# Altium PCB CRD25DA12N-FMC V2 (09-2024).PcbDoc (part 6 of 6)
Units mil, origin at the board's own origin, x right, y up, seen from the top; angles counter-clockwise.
Board outline 8000 x 8000 mil, 6 copper layers (Top Layer, Layer 2, Layer 3, Layer 4, Layer 5, Bottom Layer), stack 91 mil thick; 602 components, 333 nets, 1670 pads, 639 vias.
Unrouted connection lines stored in the file: 1.
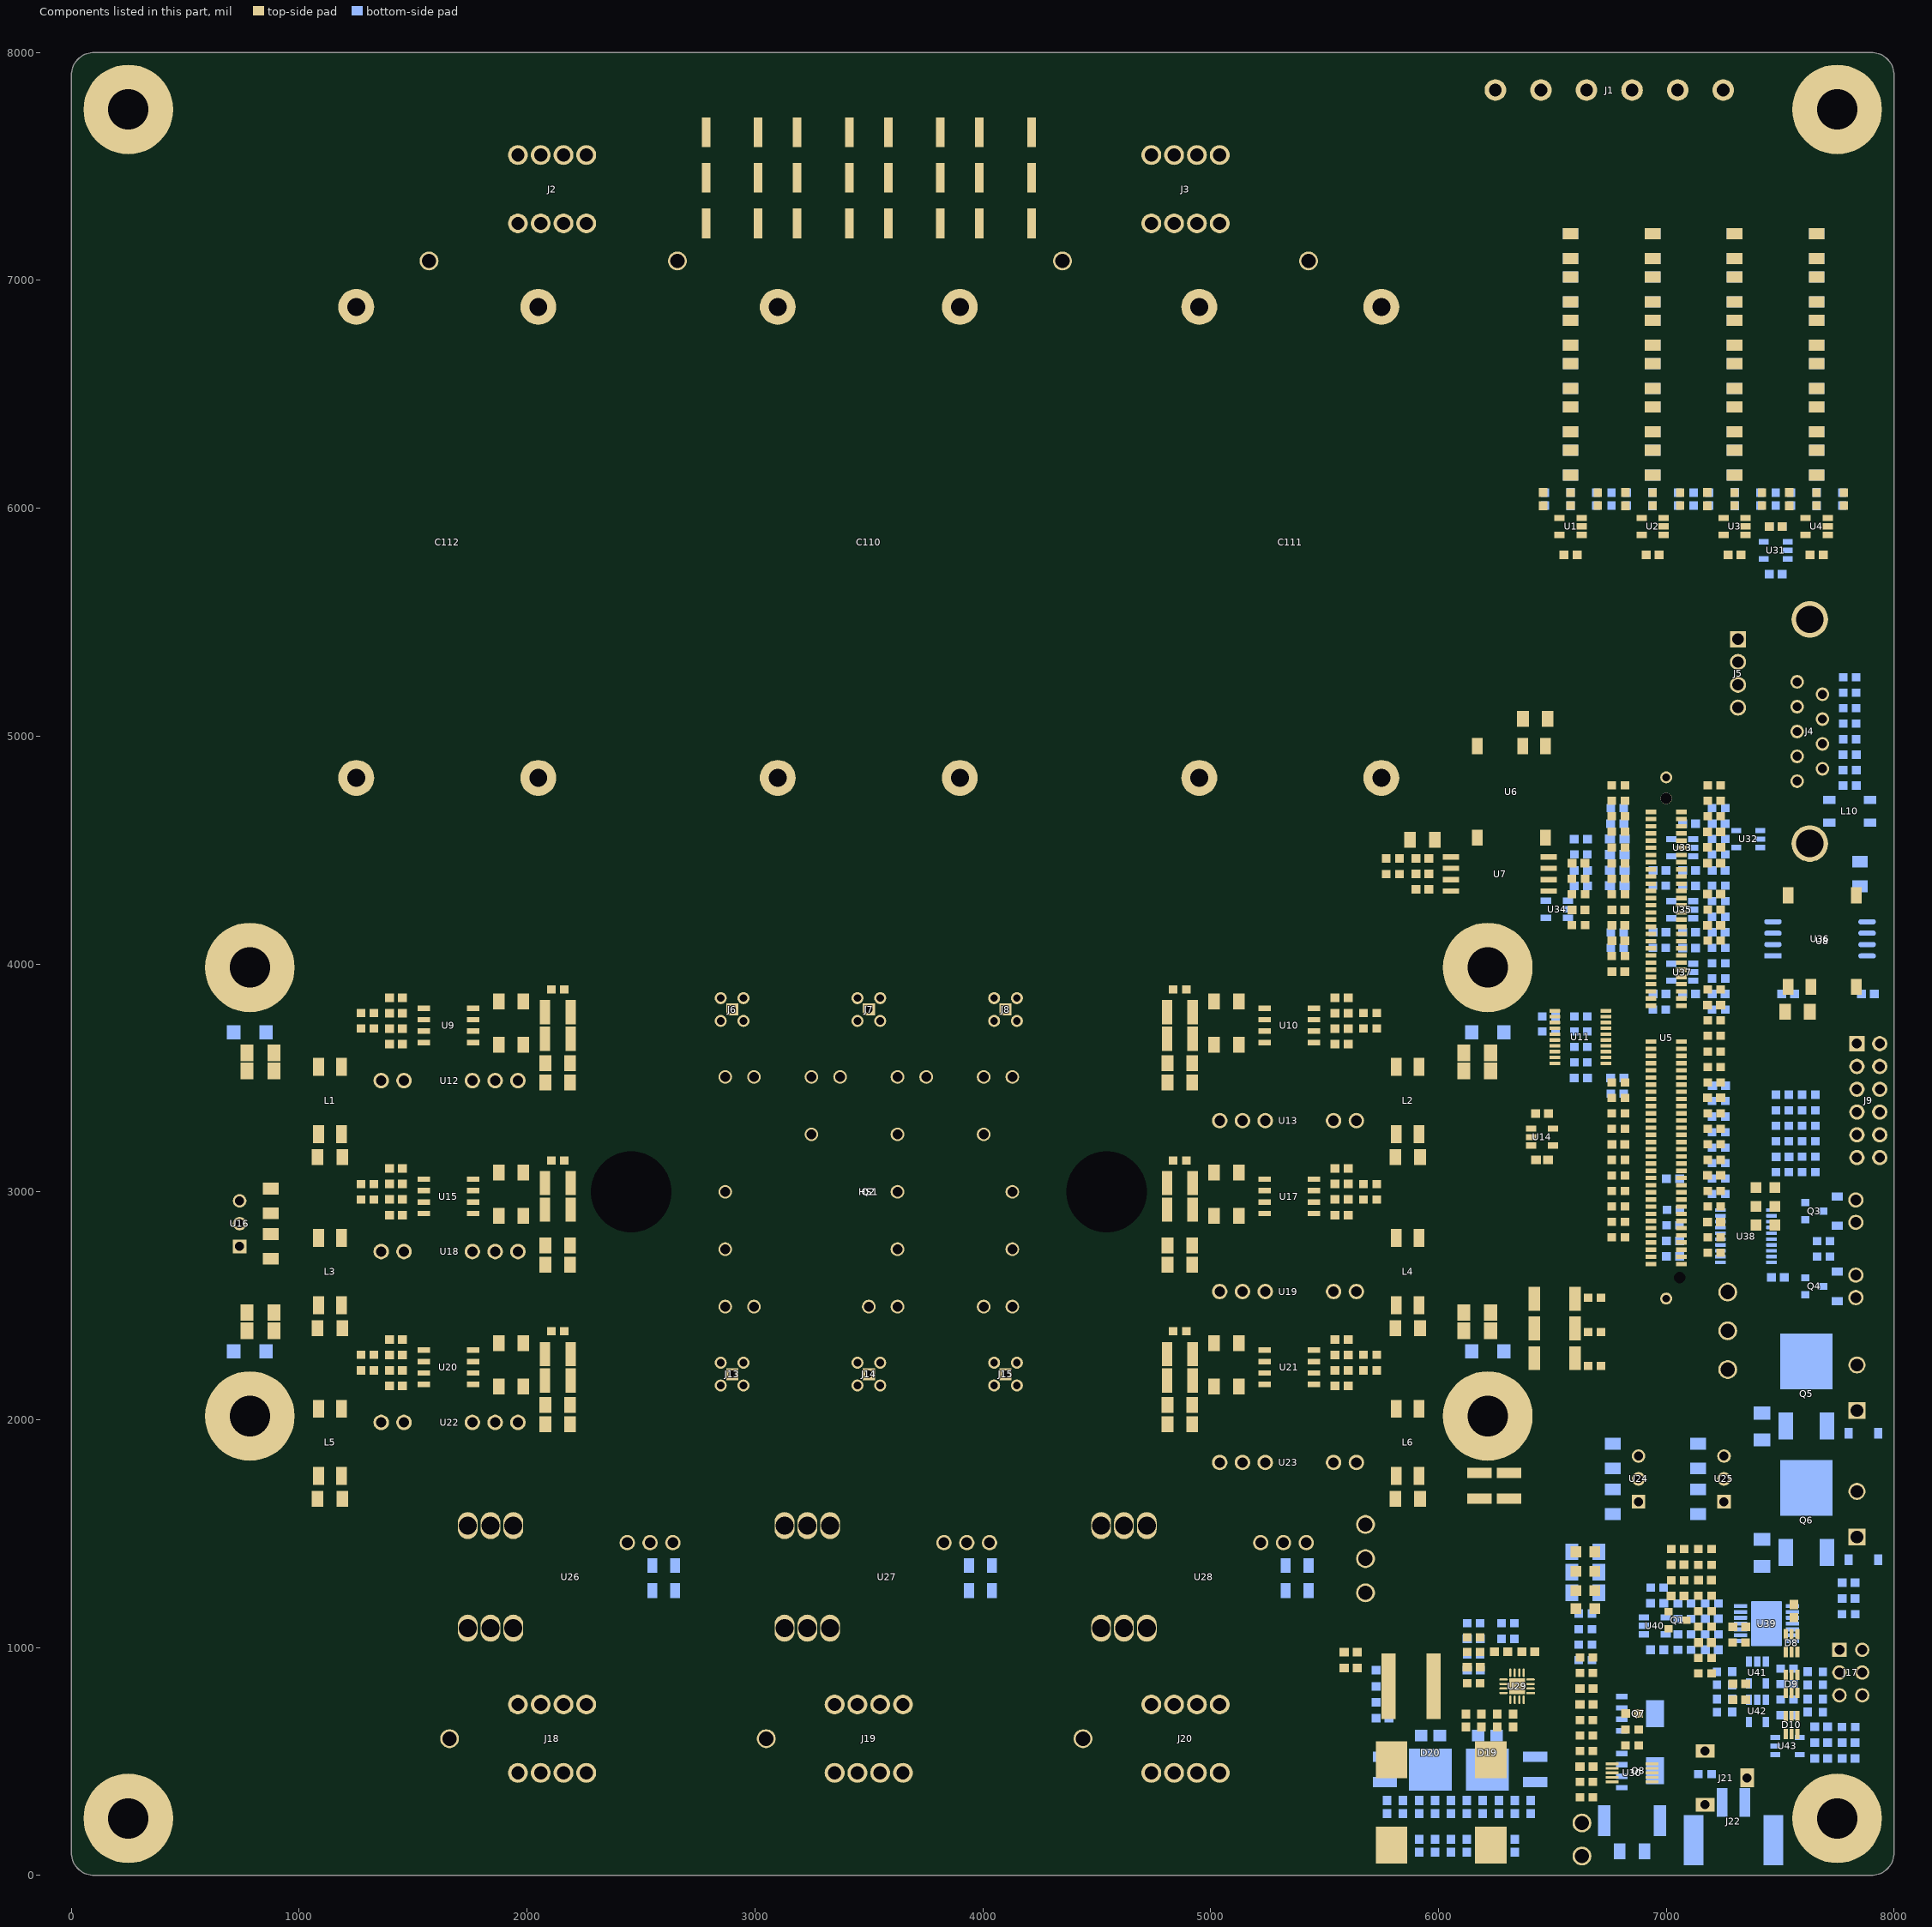
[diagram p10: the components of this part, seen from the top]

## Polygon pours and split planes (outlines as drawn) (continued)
+15V on Bottom Layer "Bottom Layer-+15V 1" (solid, pour order 1128): 3980,1334.96 3980,1489.91 ccw(c3954.91,1489.91) 3954.98,1515 3914.95,1515 ccw(c3915.07,1489.93) 3890,1489.92 3890,1405 3890,1391.3 3890,1334.98 ccw(c3915.03,1335.03) 3914.94,1310 3954.97,1310 ccw(c3954.97,1335.03)
GND on Bottom Layer "Bottom Layer-GND 2" (solid, pour order 1127): 4115,1234.92 4115,1365.14 ccw(c4067.49,1367.5) 4070.08,1415 4035,1415 ccw(c4035.07,1369.93) 3990,1370 3990,1234.92 ccw(c4037.46,1237.47) 4039.85,1190 4070.08,1190 ccw(c4069.99,1235.01)
+15V on Bottom Layer "Bottom Layer-+15V 2" (solid, pour order 1125): 2590,1334.96 2590,1489.91 ccw(c2564.91,1489.91) 2564.98,1515 2524.95,1515 ccw(c2525.07,1489.93) 2500,1489.92 2500,1405 2500,1391.3 2500,1334.98 ccw(c2525.03,1335.03) 2524.94,1310 2564.97,1310 ccw(c2564.97,1335.03)
GND on Bottom Layer "Bottom Layer-GND 3" (solid, pour order 1124): 2720,1234.92 2720,1365 ccw(c2674.92,1369.95) 2680.08,1415 2645,1415 ccw(c2645.07,1369.93) 2600,1370 2600,1234.92 ccw(c2647.46,1237.47) 2649.85,1190 2675.08,1190 ccw(c2674.99,1235.01)
NetC47_2 on Bottom Layer "Bottom Layer-NetC106_2" (solid, pour order 1122): 24 vertices, not listed, extent 1025,3090 1515.4,3540
S3 on Bottom Layer "Bottom Layer-S3" (solid, pour order 285): 21 vertices, not listed, extent 1830,3430 2225.07,3880
-3V_V_HS on Bottom Layer "Bottom Layer--3V_V_HS" (solid, pour order 1063): 1735,3474.9 ccw(c1780,3475) 1777.5,3430.07 ccw(c1775,3475) 1820,3474.91 1820,3515.4 1820.37,3515.77 cw(c1865,3510) 1859.85,3554.7 ccw(c1859.7,3600) 1905,3599.91 1905,3835.14 ccw(c1860,3835) 1860.23,3880 1779.81,3880 ccw(c1780,3835) 1735,3835 1735,3525
+15V_V_HS on Bottom Layer "Bottom Layer-+15V_V_HS" (solid, pour order 1062): 1980,3430 2005.11,3430 ccw(c2005,3475) 2050,3474.9 2050,3480.17 ccw(c2005,3480) 2005.11,3525 1979.86,3525 ccw(c1980,3480) 1935,3480 1935,3525 1935,3477.5 1935,3474.9 ccw(c1980,3475)
S2 on Bottom Layer "Bottom Layer-S2" (solid, pour order 1035): 21 vertices, not listed, extent 1830,1930 2225.07,2380
+15V_U_LS on Bottom Layer "Bottom Layer-+15V_U_LS" (solid, pour order 1030): 1980,1930 2005.11,1930 ccw(c2005,1975) 2050,1974.9 2050,1980.17 ccw(c2005,1980) 2005.11,2025 1979.86,2025 ccw(c1980,1980) 1935,1980 1935,2025 1935,1977.5 1935,1974.9 ccw(c1980,1975)
GND on Bottom Layer "Bottom Layer-GND 1" (solid, pour order 997): 6685,1694.87 ccw(c6730,1695) 6730,1650 6805,1650 6850,1695 6905,1695 ccw(c6904.9,1740.1) 6950,1740 ccw(c6904.88,1739.88) 6905,1785 6850,1785 6805,1830 6773.42,1830 6729.89,1830 ccw(c6730,1785) 6685,1785 6685,1745
+3.3V on Bottom Layer "Bottom Layer-+3.3V" (solid, pour order 985): 6855,1795 6905,1795 ccw(c6904.94,1840.06) 6950,1840 6950,1895 ccw(c6904.94,1894.94) 6905,1940 6729.86,1940 ccw(c6730,1895) 6685,1895 6685,1884.86 ccw(c6730,1885) 6730,1840 6810,1840
+12V on Bottom Layer "Bottom Layer-+12V" (solid, pour order 979): 6855,1685 6905,1685 cw(c6904.94,1639.94) 6950,1640 6950,1585 cw(c6904.94,1585.06) 6905,1540 6729.86,1540 cw(c6730,1585) 6685,1585 6685,1595.13 cw(c6730,1595) 6730,1640 6810,1640
+5V on Bottom Layer "Bottom Layer-+5V" (solid, pour order 978): 7230,1795 7280,1795 ccw(c7279.94,1840.06) 7325,1840 7325,1895 ccw(c7279.94,1894.94) 7280,1940 7104.86,1940 ccw(c7105,1895) 7060,1895 7060,1884.86 ccw(c7105,1885) 7105,1840 7185,1840
+12V on Bottom Layer "Bottom Layer-+12V 1" (solid, pour order 977): 7230,1685 7280,1685 cw(c7279.94,1639.94) 7325,1640 7325,1585 cw(c7279.94,1585.06) 7280,1540 7104.86,1540 cw(c7105,1585) 7060,1585 7060,1595.13 cw(c7105,1595) 7105,1640 7185,1640
GND on Bottom Layer "Bottom Layer-GND 1" (solid, pour order 975): 7060,1694.87 ccw(c7105,1695) 7105,1650 7180,1650 7225,1695 7280,1695 ccw(c7279.9,1740.1) 7325,1740 ccw(c7279.88,1739.88) 7280,1785 7225,1785 7180,1830 7148.42,1830 7104.89,1830 ccw(c7105,1785) 7060,1785 7060,1745
GND_ISO on Bottom Layer "Bottom Layer-GND_ISO 2" (solid, pour order 521): 7905,3810 ccw(c7904.93,3855.07) 7950,3855 7950,3930 7870,3930 7870,3810
GND on Layer 5 "Layer 5-GND" (solid, pour order 2457): 96 vertices, not listed, extent 2380,50 7950,6175
GND on Layer 5 "Layer 3-+5V_ALT" (solid, pour order 2479): 20 vertices, not listed, extent 490,1590 1575,3890
S3 on Layer 5 "Layer 5-S2" (solid, pour order 2473): 1780,3430 2180.14,3430 ccw(c2180,3475) 2225,3475 2225,3865.14 ccw(c2180,3865) 2180,3910 1779.86,3910 ccw(c1780,3865) 1735,3865 1735,3474.86 ccw(c1780,3475)
S1 on Layer 5 "Layer 5-S2" (solid, pour order 2472): 1780,2680 2180.14,2680 ccw(c2180,2725) 2225,2725 2225,3115.14 ccw(c2180,3115) 2180,3160 1779.86,3160 ccw(c1780,3115) 1735,3115 1735,2724.86 ccw(c1780,2725)
DC- on Layer 5 "Layer 3-DC-" (solid, pour order 2106): 57 vertices, not listed, extent 760,2878.55 6240,7740
S5 on Layer 5 "Layer 5-S4" (solid, pour order 2466): 4990,3880 4940,3880 4910,3910 4814.87,3910 ccw(c4815,3865) 4770,3865 4770,3449.83 ccw(c4815,3450) 4815,3405 4890,3405 5020,3275 5220.06,3275 ccw(c5220,3320) 5265,3320 5265,3825.1 ccw(c5220,3825) 5220,3870 5000,3870
S6 on Layer 5 "Layer 5-S4" (solid, pour order 2465): 4990,3130 4940,3130 4910,3160 4814.87,3160 ccw(c4815,3115) 4770,3115 4770,2699.83 ccw(c4815,2700) 4815,2655 4890,2655 5020,2525 5220.06,2525 ccw(c5220,2570) 5265,2570 5265,3075.1 ccw(c5220,3075) 5220,3120 5000,3120
GND_ISO on Layer 5 "Layer 5-GND_ISO" (solid, pour order 2434): 19 vertices, not listed, extent 7255,3810 7950,5585
W on Layer 5 "Layer 5-W" (solid, pour order 2040): 18 vertices, not listed, extent 4045.11,1000 4880.02,2775
V on Layer 5 "Layer 5-V" (solid, pour order 2038): 17 vertices, not listed, extent 2935,1000 3709.89,2775.01
U on Layer 5 "Layer 5-U" (solid, pour order 2036): 23 vertices, not listed, extent 1545,1000 2955,2775
S4 on Layer 5 "Layer 5-S4" (solid, pour order 1930): 4990,2380 4940,2380 4910,2410 4814.87,2410 ccw(c4815,2365) 4770,2365 4770,1949.83 ccw(c4815,1950) 4815,1905 4890,1905 5020,1775 5220.06,1775 ccw(c5220,1820) 5265,1820 5265,2325.1 ccw(c5220,2325) 5220,2370 5000,2370
S2 on Layer 5 "Layer 5-S2" (solid, pour order 1853): 1780,1930 2180.14,1930 ccw(c2180,1975) 2225,1975 2225,2365.14 ccw(c2180,2365) 2180,2410 1779.86,2410 ccw(c1780,2365) 1735,2365 1735,1974.86 ccw(c1780,1975)
+5V_NTC on Top Layer "Top Layer-+5V_NTC" (solid, pour order 2507): 6180,4500 ccw(c6180,4520) 6200,4520 6200,4590 ccw(c6180,4590) 6180,4610 5960,4610 ccw(c5960,4590) 5940,4590 5940,4375 6015,4375 6015,4440 6115,4440 6115,4500
GND_NTC on Top Layer "Top Layer-GND_NTC" (solid, pour order 2500): 6125,4895 ccw(c6145,4895) 6145,4875 6175,4875 ccw(c6175,4895) 6195,4895 6195,5003.23 ccw(c6180,4990) 6180,5010 6145,5010 ccw(c6145,4990) 6125,4990
+12V on Top Layer "Top Layer-+12V 5" (solid, pour order 2080): 20 vertices, not listed, extent 671.87,3355 5880,4500
GND on Top Layer "Top Layer-GND 6" (solid, pour order 1584): 6340,2235 ccw(c6375,2235) 6374.85,2200 6455.15,2200 ccw(c6455,2235) 6490,2234.83 6490,2565.17 ccw(c6455,2565) 6455.18,2600 6374.82,2600 ccw(c6375,2565) 6340,2565
NetC48_1 on Top Layer "Top Layer-NetC135_1" (solid, pour order 2471): 5970,3134.86 cw(c5924.96,3135.04) 5924.96,3090 5915,3090 cw(c5915.08,3135.08) 5870,3135 5870,3210 5870,3255 5870,3320.16 cw(c5915,3320) 5915,3365 5980,3365 cw(c5980,3320) 6025,3320.16 6025,3220 cw(c5992.54,3217.46) 5995,3185 ccw(c6007.84,3149.49) 5970.31,3145.31 5970,3140.19
NetC48_2 on Top Layer "Top Layer-NetC135_2" (solid, pour order 2470): 22 vertices, not listed, extent 5490,3090 5860,3365
GND on Top Layer "Top Layer-+12V" (solid, pour order 879): 1040,3484.87 ccw(c1085,3485) 1085,3440 1085.16,3440 ccw(c1085,3485) 1130,3485 1130,3550 1130,3567.46 1130,3610 ccw(c1085,3610) 1085,3655 ccw(c1085.08,3609.92) 1040,3610 1040,3545
G5 on Top Layer "Top Layer-G5" (solid, pour order 706): 19 vertices, not listed, extent 3705,3465.25 4850,3900
GND on Top Layer "Top Layer-GND" (solid, pour order 1476): 6485,4834.65 6495.17,4834.65 ccw(c6495,4879.65) 6540,4879.61 6540,5105 ccw(c6494.94,5104.94) 6495,5150 6485,5150 ccw(c6485.08,5104.92) 6440,5105 6440,4954.65 6440,4929.65 6440,4879.65 ccw(c6485,4879.65)
GND on Top Layer "Top Layer-GND 8" (solid, pour order 2317): 6075,154.86 ccw(c6130,155) 6130,100 6165,100 6165,55 6295,55 6295,100 6350,100 ccw(c6350,155) 6405,155 6405,160.03 ccw(c6350,160) 6362.76,213.5 6117.24,213.5 ccw(c6130,160) 6075,160
-15V on Top Layer "Top Layer--15V" (solid, pour order 2271): 5565,95 ccw(c5610,95) 5610,50 5979.19,50.01 ccw(c5980,95) 6025,94.79 6025,164.59 ccw(c5980,165) 5979.63,210 5610,210 ccw(c5609.99,165.01) 5565,165 5565,95.13 ccw(c5608.24,95)
NetC105_2 on Top Layer "Top Layer-NetC202_2" (solid, pour order 2267): 6130,605 6215,605 6215,680 6055,680 6055,630 5763,630 5735,630 ccw(c5735,585) 5690,584.73 5690,554.81 ccw(c5735,555) 5735,510 5860,510 5860,535 6130,535
NetC107_2 on Top Layer "NONET_L-01_P-001" (solid, pour order 2115): 6140,595 6140,535 6385,535 6385,680 6230,680 6230,595
GND on Top Layer "NONET_L-01_P-001" (solid, pour order 2129): 6365,810 6365,740 6435,740 6435,810
NetC105_1 on Top Layer "NONET_L-01_P-001" (solid, pour order 2113): 5945,1000 5945,640 6040,640 6040,705 6350,705 6350,795 6305,795 6305,810 6100,810 6055,855 6055,1000
+12V on Top Layer "Top Layer-+12V 4" (solid, pour order 2263): 5690,685 ccw(c5735,685) 5735.13,640 5770.09,640 ccw(c5770,685) 5815,684.83 5814.99,1014.26 ccw(c5770,1015) 5770.13,1060 5735.26,1060 ccw(c5734.99,1015.01) 5690,1015 5690,1014.94 5690,685.65 ccw(c5733.98,685.01)
DC- on Top Layer "Top Layer-DC-" (solid, pour order 2292): 4265,2935 4265,2975.11 ccw(c4210,2975) 4208.55,3029.98 2789.73,3030 ccw(c2790,2975) 2735,2975 2735,2934.89 ccw(c2790,2935) 2788.99,2880.01 4210,2880 ccw(c4210,2935)
DC+ on Top Layer "Top Layer-DC+" (solid, pour order 2282): 2735.23,3240 ccw(c2790,3245) 2791.01,3190.01 4210,3190 ccw(c4210,3245) 4265,3245 4265,3260 ccw(c4210,3260) 4210,3315 2915,3315.02 2915,3290 2790,3290 ccw(c2790,3235)
+5V on Top Layer "Top Layer-+5V 1" (solid, pour order 2162): 17 vertices, not listed, extent 6755,615 7490,1940
GND on Top Layer "Top Layer-GND 5" (solid, pour order 1354): 6095.12,1615 cw(c6095,1640) 6070,1639.9 6070,1680.09 cw(c6095,1680) 6094.88,1705 6230,1705 6385.12,1705 cw(c6385,1680) 6410,1680.14 6410,1639.9 cw(c6385.12,1639.88) 6385.11,1615
G4 on Top Layer "Top Layer-G4" (solid, pour order 696): 23 vertices, not listed, extent 3605,1890 4870,2535
+15V_W_HS on Top Layer "Top Layer-+15V_W_HS 1" (solid, pour order 737): 5190,3775 5165,3800 5095,3800 5095,3870 5220.13,3870 cw(c5220,3825) 5265,3825 5265,3775
G5H on Top Layer "G5H_L01_P733" (solid, pour order 733): 4980,3852.79 4980,3790 5160,3790 5185,3765 5265,3765 5265,3735 4895,3735 4895,3852.8
G3 on Top Layer "Top Layer-G3" (solid, pour order 705): 22 vertices, not listed, extent 2130,3455 3405,4100
G1 on Top Layer "Top Layer-G1" (solid, pour order 703): 2215,3085 2580,3450 2915,3450 2943.97,3450 2965.09,3450 ccw(c2965,3495) 3008.94,3485.28 3008.94,3560 2535,3560 2130,3155 2130,2810 2215,2810
G6 on Top Layer "Top Layer-G6" (solid, pour order 699): 18 vertices, not listed, extent 3955,2445 4870,3150
G2 on Top Layer "Top Layer-G2" (solid, pour order 692): 2175,2350 2175,2400 2150,2400 2150,2350 2130,2350 2130,2110 2210,2110 2210,2165 2490,2445 2999.86,2445 ccw(c3000,2490) 3045,2490 3045,2510.16 ccw(c3000,2510) 3000,2555 2445,2555 2240,2350
+5V_ISO on Top Layer "Top Layer-+5V_ISO" (solid, pour order 1576): 7829.79,4235.21 7883.86,4235.21 ccw(c7880,4270) 7915,4269.83 7915,4370.18 ccw(c7880,4370) 7880.19,4405 7829.79,4405 ccw(c7829.99,4370.01) 7795,4370.01 7795,4270 ccw(c7829.89,4270.1)
GND on Top Layer "Top Layer-GND 7" (solid, pour order 1568): 7465,3735 ccw(c7500,3735) 7499.85,3700 7540.15,3700 ccw(c7540,3735) 7575,3734.8 7575,3930.15 ccw(c7540,3930) 7540.17,3965 7499.83,3965 ccw(c7500,3930) 7465,3930.12
+3.3V on Top Layer "Top Layer-+3.3V" (solid, pour order 1560): 7585,3734.81 ccw(c7620,3735) 7619.85,3700 7640.17,3700 ccw(c7640,3735) 7675,3734.92 7675,3929.81 ccw(c7639.81,3929.81) 7640,3965 7619.76,3965 ccw(c7620,3930) 7585,3930.17
+3.3V on Top Layer "Top Layer-+5V" (solid, pour order 1377): 6345.39,4879.53 ccw(c6390.38,4879.65) 6387.89,4834.72 ccw(c6385.39,4879.65) 6430.39,4879.65 6430.39,5113.21 ccw(c6388.74,5107.96) 6385.91,5149.84 ccw(c6390.42,5105.04) 6345.39,5105
GND_ISO on Top Layer "Top Layer-GND_ISO" (solid, pour order 654): 7855,3810 7880,3810 7905.1,3810 ccw(c7905,3855) 7950,3854.9 7950,3965.17 ccw(c7905,3965) 7905.14,4010 7839.81,4010 ccw(c7840,3965) 7795,3965 7795,3854.86 ccw(c7840,3855) 7840,3810 7855,3810
+12V on Top Layer "Top Layer-+12V 2" (solid, pour order 796): 5870,3484.87 ccw(c5915,3485) 5915,3440 5915.17,3440 ccw(c5915,3485) 5960,3485 5960,3550 5960,3567.46 5960,3610 ccw(c5915,3610) 5915,3655 ccw(c5915.08,3609.92) 5870,3610 5870,3545
+15V_W_HS on Top Layer "Top Layer-+15V_W_HS" (solid, pour order 739): 5040.1,3280 ccw(c5040,3325) 5085,3325 5085,3470.17 ccw(c5040,3470) 5040,3515 4895,3515 4895,3410 5025,3280
+15V_W_LS on Top Layer "Top Layer-+15V_W_LS" (solid, pour order 747): 5040.1,2530 ccw(c5040,2575) 5085,2575 5085,2720.16 ccw(c5040,2720) 5040,2765 4895,2765 4895,2650 5015,2530
+15V_V_LS on Top Layer "Top Layer-+15V_V_LS" (solid, pour order 731): 5040.1,1780 ccw(c5040,1825) 5085,1825 5085,1970.16 ccw(c5040,1970) 5040,2015 4895,2015 4895,1900 5015,1780
NetHS1_3 on Top Layer "Top Layer-NetHS1_3" (solid, pour order 1333): 6315,1715 6365.13,1715 ccw(c6365,1760) 6410,1760 6410,2015 6070,2015 6070,1810 6070,1760 ccw(c6115,1760) 6115,1715 6180,1715
+15V_V_HS on Top Layer "Top Layer-+15V_V_HS" (solid, pour order 669): 19 vertices, not listed, extent 1735,3430 2110,3680
G3H on Top Layer "G3H_L01_P527" (solid, pour order 527): 1820,3690 2020,3690 2020,3610 2105,3610 2105,3725 1735,3725 1735,3690
NetC69_1 on Top Layer "Top Layer-NetC157_1" (solid, pour order 1244): 21 vertices, not listed, extent 1140,2340 1515,2790
NetC47_1 on Top Layer "Top Layer-NetC157_1" (solid, pour order 987): 21 vertices, not listed, extent 1140,3090 1515,3540
NetC87_1 on Top Layer "Top Layer-NetC157_1" (solid, pour order 874): 21 vertices, not listed, extent 1140,1590 1515,2040
NetC47_2 on Top Layer "Top Layer-NetC106_2" (solid, pour order 894): 1085,3090 ccw(c1087.43,3132.58) 1130,3130 1130,3205 1130,3380.13 ccw(c1085,3380) 1085,3425 1069.86,3425 ccw(c1069.92,3380.08) 1025,3380.13 1025,3315 1025,3130 ccw(c1077.84,3142.84) 1065,3090
+5V_ALT on Top Layer "Top Layer-+5V_ALT" (solid, pour order 986): 900,3075 cw(c900,3030) 945,3030.13 945,3010 cw(c899.94,3010.06) 900,2965 840,2965 835,2965 785,2915 715,2915 cw(c715.06,2960.06) 670,2960 670,3025 670,3030 cw(c715.07,3029.93) 715,3075
GND on Top Layer "Top Layer-GND 4" (solid, pour order 899): 18 vertices, not listed, extent 670,2770 945,2950
+12V on Top Layer "Top Layer-+12V 3" (solid, pour order 898): 900,2645 ccw(c900,2690) 945,2689.86 945,2710 ccw(c899.94,2709.94) 900,2755 840,2755 835,2755 785,2805 715,2805 ccw(c715.06,2759.94) 670,2760 670,2695 670,2690 ccw(c715.07,2690.07) 715,2645
+12V on Top Layer "Top Layer-+12V" (solid, pour order 877): 1140,3484.87 ccw(c1185,3485) 1185,3440 1185.16,3440 ccw(c1185,3485) 1230,3485 1230,3550 1230,3567.46 1230,3610 ccw(c1185,3610) 1185,3655 ccw(c1185.08,3609.92) 1140,3610 1140,3545
NetC87_2 on Top Layer "Top Layer-NetC157_2" (solid, pour order 876): 1085,1590 ccw(c1087.43,1632.58) 1130,1630 1130,1705 1130,1880.13 ccw(c1085,1880) 1085,1925 1069.86,1925 ccw(c1069.92,1880.08) 1025,1880.13 1025,1815 1025,1635 ccw(c1070,1635) 1070,1590
NetC69_2 on Top Layer "Top Layer-NetC136_2" (solid, pour order 873): 1085,2340 ccw(c1087.43,2382.58) 1130,2380 1130,2455 1130,2630.13 ccw(c1085,2630) 1085,2675 1069.86,2675 ccw(c1069.92,2630.08) 1025,2630.13 1025,2565 1025,2380 ccw(c1077.84,2392.84) 1065,2340
GND on Top Layer "Top Layer-+12V" (solid, pour order 872): 1040,2734.87 ccw(c1085,2735) 1085,2690 1085.16,2690 ccw(c1085,2735) 1130,2735 1130,2800 1130,2817.46 1130,2860 ccw(c1085,2860) 1085,2905 ccw(c1085.08,2859.92) 1040,2860 1040,2795
+12V on Top Layer "Top Layer-+12V" (solid, pour order 842): 1140,2734.87 ccw(c1185,2735) 1185,2690 1185.16,2690 ccw(c1185,2735) 1230,2735 1230,2800 1230,2817.46 1230,2860 ccw(c1185,2860) 1185,2905 ccw(c1185.08,2859.92) 1140,2860 1140,2795
GND on Top Layer "Top Layer-+12V" (solid, pour order 841): 1040,1984.87 ccw(c1085,1985) 1085,1940 1085.16,1940 ccw(c1085,1985) 1130,1985 1130,2050 1130,2067.46 1130,2110 ccw(c1085,2110) 1085,2155 ccw(c1085.08,2109.92) 1040,2110 1040,2045
+12V on Top Layer "Top Layer-+12V" (solid, pour order 840): 1140,1984.87 ccw(c1185,1985) 1185,1940 1185.16,1940 ccw(c1185,1985) 1230,1985 1230,2050 1230,2067.46 1230,2110 ccw(c1185,2110) 1185,2155 ccw(c1185.08,2109.92) 1140,2110 1140,2045
NetC88_1 on Top Layer "Top Layer-NetC156_1" (solid, pour order 839): 5970,1634.86 cw(c5924.96,1635.04) 5924.96,1590 5915,1590 cw(c5915.08,1635.08) 5870,1635 5870,1710 5870,1755 5870,1820.16 cw(c5915,1820) 5915,1865 5980,1865 cw(c5980,1820) 6025,1820.16 6025,1720 cw(c5992.54,1717.46) 5995,1685 ccw(c6007.84,1649.49) 5970.31,1645.31 5970,1640.19
NetC88_2 on Top Layer "Top Layer-NetC156_2" (solid, pour order 815): 22 vertices, not listed, extent 5490,1590 5860,1865
GND on Top Layer "Top Layer-GND 1" (solid, pour order 814): 5770,1984.87 ccw(c5815,1985) 5815,1940 5815.17,1940 ccw(c5815,1985) 5860,1985 5860,2050 5860,2067.46 5860,2110 ccw(c5815,2110) 5815,2155 ccw(c5815.08,2109.92) 5770,2110 5770,2045
+12V on Top Layer "Top Layer-+12V" (solid, pour order 813): 5870,1984.87 ccw(c5915,1985) 5915,1940 5915.17,1940 ccw(c5915,1985) 5960,1985 5960,2050 5960,2067.46 5960,2110 ccw(c5915,2110) 5915,2155 ccw(c5915.08,2109.92) 5870,2110 5870,2045
GND on Top Layer "Top Layer-GND 2" (solid, pour order 812): 5770,2734.87 ccw(c5815,2735) 5815,2690 5815.17,2690 ccw(c5815,2735) 5860,2735 5860,2800 5860,2817.46 5860,2860 ccw(c5815,2860) 5815,2905 ccw(c5815.08,2859.92) 5770,2860 5770,2795
+12V on Top Layer "Top Layer-+12V 1" (solid, pour order 811): 5870,2734.87 ccw(c5915,2735) 5915,2690 5915.17,2690 ccw(c5915,2735) 5960,2735 5960,2800 5960,2817.46 5960,2860 ccw(c5915,2860) 5915,2905 ccw(c5915.08,2859.92) 5870,2860 5870,2795
NetC70_1 on Top Layer "Top Layer-NetC135_1" (solid, pour order 810): 5970,2384.86 cw(c5924.96,2385.04) 5924.96,2340 5915,2340 cw(c5915.08,2385.08) 5870,2385 5870,2460 5870,2505 5870,2570.16 cw(c5915,2570) 5915,2615 5980,2615 cw(c5980,2570) 6025,2570.16 6025,2470 cw(c5992.54,2467.46) 5995,2435 ccw(c6007.84,2399.49) 5970.31,2395.31 5970,2390.19
NetC70_2 on Top Layer "Top Layer-NetC135_2" (solid, pour order 808): 22 vertices, not listed, extent 5490,2340 5860,2615
GND on Top Layer "Top Layer-GND 3" (solid, pour order 804): 5770,3484.87 ccw(c5815,3485) 5815,3440 5815.17,3440 ccw(c5815,3485) 5860,3485 5860,3550 5860,3567.46 5860,3610 ccw(c5815,3610) 5815,3655 ccw(c5815.08,3609.92) 5770,3610 5770,3545
-3V_W_LS on Top Layer "Top Layer--3V_W_LS" (solid, pour order 787): 25 vertices, not listed, extent 4895,2530.28 5265,2930
S6 on Top Layer "NONET_L-01_P-001" (solid, pour order 746): 4990,2930 4990,2860 5086.63,2860 5086.63,2930
+15V_W_LS on Top Layer "Top Layer-+15V_W_LS 1" (solid, pour order 745): 5190,3025 5165,3050 5095,3050 5095,3120 5220.13,3120 cw(c5220,3075) 5265,3075 5265,3025
S6 on Top Layer "NONET_L-01_P-001" (solid, pour order 744): 4785,2800 4785,2645 4880,2645 4880,2800
S6 on Top Layer "NONET_L-01_P-001" (solid, pour order 743): 4990,3120 4990,3050 5086.63,3050 5086.63,3120
G6L on Top Layer "G6L_L01_P742" (solid, pour order 742): 5180,2940 4980,2940 4980,2860 4895,2860 4895,2975 5265,2975 5265,2940
G6H on Top Layer "G6H_L01_P741" (solid, pour order 741): 4980,3102.79 4980,3040 5160,3040 5185,3015 5265,3015 5265,2985 4895,2985 4895,3102.8
-3V_W_HS on Top Layer "Top Layer--3V_W_HS" (solid, pour order 740): 21 vertices, not listed, extent 4895,3280.28 5265,3680
S5 on Top Layer "NONET_L-01_P-001" (solid, pour order 738): 4990,3680 4990,3610 5086.63,3610 5086.63,3680
S5 on Top Layer "NONET_L-01_P-001" (solid, pour order 736): 4785,3600 4785,3445 4880,3445 4880,3600
S5 on Top Layer "NONET_L-01_P-001" (solid, pour order 735): 4990,3870 4990,3800 5086.63,3800 5086.63,3870
G5L on Top Layer "G5L_L01_P734" (solid, pour order 734): 5180,3690 4980,3690 4980,3610 4895,3610 4895,3725 5265,3725 5265,3690
-3V_V_LS on Top Layer "Top Layer--3V_V_LS" (solid, pour order 732): 21 vertices, not listed, extent 4895,1780.28 5265,2180
S4 on Top Layer "NONET_L-01_P-001" (solid, pour order 725): 4990,2180 4990,2110 5086.63,2110 5086.63,2180
+15V_V_LS on Top Layer "Top Layer-+15V_V_LS 1" (solid, pour order 716): 5190,2275 5165,2300 5095,2300 5095,2370 5220.13,2370 cw(c5220,2325) 5265,2325 5265,2275
S4 on Top Layer "NONET_L-01_P-001" (solid, pour order 714): 4785,2100 4785,1945 4880,1945 4880,2100
S4 on Top Layer "NONET_L-01_P-001" (solid, pour order 713): 4990,2370 4990,2300 5086.63,2300 5086.63,2370
G4L on Top Layer "G4L_L01_P711" (solid, pour order 711): 5180,2190 4980,2190 4980,2110 4895,2110 4895,2225 5265,2225 5265,2190
G4H on Top Layer "G4H_L01_P710" (solid, pour order 710): 4980,2352.79 4980,2290 5160,2290 5185,2265 5265,2265 5265,2235 4895,2235 4895,2352.8
U_OUT on Top Layer "Layer 2-U_OUT" (solid, pour order 709): 25 vertices, not listed, extent 1545,340 2455,1620
W_OUT on Top Layer "Layer 2-W_OUT" (solid, pour order 708): 25 vertices, not listed, extent 4325,340 5235,1620
V_OUT on Top Layer "Layer 2-V_OUT" (solid, pour order 707): 25 vertices, not listed, extent 2935,340 3845,1620
+15V_U_LS on Top Layer "Top Layer-+15V_U_LS" (solid, pour order 688): 17 vertices, not listed, extent 1735,1930 2110,2180
-3V_U_LS on Top Layer "Top Layer--3V_U_LS" (solid, pour order 684): 1810,2275 1835,2300 1905,2300 1905,2370 1779.87,2370 ccw(c1780,2325) 1735,2325 1735,2275
S2 on Top Layer "NONET_L-01_P-001" (solid, pour order 683): 2010,2370 2010,2300 1913.37,2300 1913.37,2370
S2 on Top Layer "NONET_L-01_P-001" (solid, pour order 682): 2010,2180 2010,2110 1913.37,2110 1913.37,2180
-3V_U_LS on Top Layer "NONET_L-01_P-001" (solid, pour order 681): 2105,2100 2105,2030 2010,2030 2010,2100
S2 on Top Layer "NONET_L-01_P-001" (solid, pour order 680): 2215,2100 2215,1945 2120,1945 2120,2100
G2H on Top Layer "G2H_L01_P679" (solid, pour order 679): 1820,2190 2020,2190 2020,2110 2105,2110 2105,2225 1735,2225 1735,2190
G2L on Top Layer "G2L_L01_P678" (solid, pour order 678): 2020,2352.79 2020,2290 1840,2290 1815,2265 1735,2265 1735,2235 2105,2235 2105,2352.8
+15V_U_HS on Top Layer "Top Layer-+15V_U_HS" (solid, pour order 677): 23 vertices, not listed, extent 1735,2645 2110,2930
-3V_U_HS on Top Layer "Top Layer--3V_U_HS" (solid, pour order 676): 1810,3025 1835,3050 1905,3050 1905,3120 1779.87,3120 ccw(c1780,3075) 1735,3075 1735,3025
S1 on Top Layer "NONET_L-01_P-001" (solid, pour order 675): 2010,3120 2010,3050 1913.37,3050 1913.37,3120
S1 on Top Layer "NONET_L-01_P-001" (solid, pour order 674): 2010,2930 2010,2860 1913.37,2860 1913.37,2930
-3V_U_HS on Top Layer "NONET_L-01_P-001" (solid, pour order 673): 2105,2850 2105,2780 2010,2780 2010,2850
S1 on Top Layer "NONET_L-01_P-001" (solid, pour order 672): 2215,2800 2215,2645 2120,2645 2120,2800
G1H on Top Layer "G1H_L01_P671" (solid, pour order 671): 1820,2940 2020,2940 2020,2860 2105,2860 2105,2975 1735,2975 1735,2940
G1L on Top Layer "G1L_L01_P670" (solid, pour order 670): 2020,3102.79 2020,3040 1840,3040 1815,3015 1735,3015 1735,2985 2105,2985 2105,3102.8
S3 on Top Layer "NONET_L-01_P-001" (solid, pour order 658): 2010,3870 2010,3800 1913.37,3800 1913.37,3870
-3V_V_HS on Top Layer "Top Layer--3V_V_HS" (solid, pour order 668): 1810,3775 1835,3800 1905,3800 1905,3870 1779.87,3870 ccw(c1780,3825) 1735,3825 1735,3775
G3L on Top Layer "G3L_L01_P403" (solid, pour order 403): 2020,3852.79 2020,3790 1840,3790 1815,3765 1735,3765 1735,3735 2105,3735 2105,3852.8
S3 on Top Layer "NONET_L-01_P-001" (solid, pour order 657): 2010,3680 2010,3610 1913.37,3610 1913.37,3680
-3V_V_HS on Top Layer "NONET_L-01_P-001" (solid, pour order 656): 2105,3600 2105,3530 2010,3530 2010,3600
S3 on Top Layer "NONET_L-01_P-001" (solid, pour order 655): 2215,3600 2215,3445 2120,3445 2120,3600

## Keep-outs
Top Layer:
  lines w10: 3720.01,2054.2 ccw(c3770,2055) 3770.8,2005.01
Layer 2:
  circle w10: c7000,4726.18 r28.16
  circle w10: c7059.06,2623.82 r28.16
  lines w10: 1780,2315 1805,2315 ; 1780,3015 1805,3015 ; 1780,3715 1805,3715
Layer 3:
  circle w10: c7000,4726.18 r28.16
  circle w10: c7059.06,2623.82 r28.16
Layer 4:
  circle w10: c7000,4726.18 r28.16
  circle w10: c7059.06,2623.82 r28.16
Layer 5:
  circle w10: c7000,4726.18 r28.16
  circle w10: c7059.06,2623.82 r28.16

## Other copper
Layer 3:
  pour cut-out: 2787,3975 ccw(c2794.74,3905.26) 2725,3897.5 2725,3446.67 ccw(c2794.78,3444.78) 2792.89,3375 3040,3375 cw(c3040.01,3295.01) 3120,3295 3120,3195 ccw(c3190,3195) 3190,3125 4060,3125 ccw(c4060,3195) 4130,3195 4130,3300 cw(c4205,3300) 4205,3375 ccw(c4205,3445) 4275,3445 4275,3905 ccw(c4205.01,3905.01) 4205,3975
Layer 4:
  pour cut-out: 2787,3975 ccw(c2794.74,3905.26) 2725,3897.5 2725,3446.67 ccw(c2794.78,3444.78) 2792.89,3375 4204.85,3375 ccw(c4205,3445) 4275,3445 4275,3905 ccw(c4205.01,3905.01) 4205,3975
Layer 5:
  pour cut-out: 2787,3975 ccw(c2794.74,3905.26) 2725,3897.5 2725,3446.67 ccw(c2794.78,3444.78) 2792.89,3375 3040,3375 cw(c3040.01,3295.01) 3120,3295 3120,3195 ccw(c3190,3195) 3190,3125 4060,3125 ccw(c4060,3195) 4130,3195 4130,3300 cw(c4205,3300) 4205,3375 ccw(c4205,3445) 4275,3445 4275,3905 ccw(c4205.01,3905.01) 4205,3975
Bottom Layer:
  pour cut-out: 2820,4010 ccw(c2819.97,3890.02) 2700,3890 2700,3505 ccw(c2870,3505) 2870,3335 4135,3335 ccw(c4135.18,3499.82) 4300,3500 4300,3895 ccw(c4185.02,3895.02) 4185,4010

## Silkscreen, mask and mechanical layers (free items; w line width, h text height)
Top Overlay:
  drawing of 153 lines, arcs and shapes, not listed
  text "+" at 2026.69,7914.65 h250 r180
  text "-" at 4806.69,7914.96 h250 r180
  text "W-" at 6200.02,7585 h60
  text "W+" at 6400.02,7585 h60
  text "V-" at 6600.02,7585 h60
  text "V+" at 6800.02,7585 h60
  text "U-" at 7000.02,7585 h60
  text "U+" at 7200.02,7585 h60
  text "DC+" at 1490.03,7170 h60
  text "DC+" at 2580.03,7170 h60
  text "DC-" at 4270.03,7170 h60
  text "DC-" at 5350.03,7170 h60
  text "H" at 696.25,7076.88 h900
  text "CAUTION / HIGH VOLTAGE" at 660.11,7019.04 h60
  text "+5VISO" at 6971.56,5407.51 h35
  text "25kW WolfPACK FM3 Six-Pack Inverter / PN CRD25DA12N-FMC, V2.0 09/2024" at 1763.05,5355 h100
  text "CANH" at 7035.71,5307.51 h35
  text "CANL" at 7035.71,5207.51 h35
  text "GNDISO" at 6971.56,5107.51 h35
  text "U-HS / (G1)" at 2780.04,3880 h60
  text "V-HS / (G3)" at 3380.04,3880 h60
  text "W-HS / (G5)" at 3980.04,3880 h60
  text "(OFF)" at 2231,3747 h35
  text "(ON)" at 4658.2,3747 h35
  text "PWR" at 7514,3633.35 h35 r90
  text "(ON)" at 2231,3631 h35
  text "(OFF)" at 4623.21,3631 h35
  text "3.3" at 7546.26,3631 h35
  text "+5" at 7680.84,3631 h35
  text "A0" at 7560.84,3531 h35
  text "A1" at 7686.67,3531 h35
  text "ADC" at 7514,3513.35 h35 r90
  text "7A" at 7560.84,3431 h35
  text "7B" at 7680.84,3431 h35
  text "PWM" at 7514,3393.35 h35 r90
  text "35" at 7560.84,3331 h35
  text "54" at 7680.84,3331 h35
  text "55" at 7560.84,3231 h35
  text "57" at 7680.84,3231 h35
  text "GPIO" at 7514,3228.77 h35 r90
  text "GND" at 7543.35,3131 h35
  text "+12" at 7666.26,3131 h35
  text "PWR" at 7514,3105.7 h35 r90
  text "T-AMB" at 6220.09,3025 h60
  text "+" at 7647.49,2963.34 h35 r90
  text "2" at 7647.49,2928.34 h35 r90
  text "-" at 7647.49,2893.34 h35 r90
  text "(OFF)" at 2336,2706 h35
  text "(ON)" at 4553.2,2706 h35
  text "FANS" at 7645,2640.04 h60 r90
  text "(ON)" at 2336,2591 h35
  text "(OFF)" at 4518.21,2591 h35
  text "+" at 7647.49,2583.34 h35 r90
  text "1" at 7647.49,2554.17 h35 r90
  text "3.3V" at 7350,2535 h60
  text "-" at 7647.49,2513.34 h35 r90
  text "+5V" at 7350,2365 h60
  text "2-" at 7625,2250.02 h60 r90
  text "(OFF)" at 2231,2247 h35
  text "(ON)" at 4658.2,2247 h35
  text "GND" at 7350,2195 h60
  text "(ON)" at 2231,2131 h35
  text "(OFF)" at 4623.21,2131 h35
  text "2+" at 7625,2050.02 h60 r90
  text "U-LS / (G2)" at 2780.04,1944.04 h60
  text "V-LS / (G4)" at 3380.04,1944.04 h60
  text "W-LS / (G6)" at 3980.04,1944.04 h60
  text "RELAYS" at 7530,1725.06 h60 r90
  text "1-" at 7625,1640.01 h60 r90
  text "+15V" at 5770,1515 h60
  text "1+" at 7625,1440.01 h60 r90
  text "+3.3V" at 6250.09,1390 h60
  text "-15V" at 5770,1365 h60
  text "+5V" at 6360.05,1305 h60
  text "+15V" at 6310.07,1220 h60
  text "GND" at 5770,1215 h60
  text "-15V" at 6310.07,1140 h60
  text "U" at 1640.01,685 h60
  text "V" at 3030.01,685 h60
  text "W" at 4420.01,685 h60
  text "1" at 7499,534.17 h35 r90
  text "2" at 7564,528.34 h35 r90
  text "3" at 7499,478.34 h35 r90
  text "4" at 7564,478.34 h35 r90
  text "5" at 7499,428.34 h35 r90
  text "6" at 7564,428.34 h35 r90
  text "-" at 7465,364.99 h60 r180
  text "+12V" at 6720,205 h60
  text "+" at 7465,95 h60 r180
  text "U" at 2026.69,85 h250
  text "V" at 3416.69,85 h250
  text "W" at 4806.69,85 h250
  text "GND" at 6720,60 h60
  text "+12V" at 7496,16 h35
Bottom Overlay:
  lines w8: 6614.61,6089.61 6623.8,6098.8 ; 6974.61,6089.61 6983.8,6098.8 ; 7277.48,4717.7 7295.2,4717.7 ; 7334.61,6089.61 7343.8,6098.8 ; 7694.61,6089.61 7703.8,6098.8 ; 7880,755 7880,669 7990,669 ; 7885,821 7992,821 7992,669
  lines w10: 5720,305 5740.39,305 ; 5790,130 5810.39,130 ; 6541.74,4445 6543.04,4446.3 6577.52,4446.3 ; 6900,4015 6921.3,4036.3 6922.52,4036.3 ; 6900,4288 6921.3,4309.3 ; 6935,1300 6935,1350 ; 7080,1230 7080,1250 ; 7170,745 7185,745 ; 7170,865 7185,865 ; 7225,1230 7225,1250 ; 7310,465 7235,465 7235,635 7400,635 7400,465 ; 7395,620 7433.22,620 7482.52,669.3 ; 7508.68,3461.14 7508.68,3480 ; 7545,310 7415,310 7415,465 7555,465 ; 7555,360 7555,465 ; 7625,3394 7625,3407 ; 7632.5,477.5 7620,465 7555,465 ; 7725,717.5 7874.5,717.5 ; 5135,195 5715,195 5715,375 5135,375 5135,195 ; 5315,15 5785,15 5785,195 5315,195 5315,15 ; 6205,4315 6541.74,4315 6541.74,4575 6205,4575 6205,4315 ; 6580,3900 6900,3900 6900,4020 6580,4020 6580,3900 ; 6620,4185 6900,4185 6900,4295 6620,4295 6620,4185 ; 6832.5,1350 6997.5,1350 6997.5,1470 6832.5,1470 6832.5,1350 ; 7017.5,1250 7182.5,1250 7182.5,1470 7017.5,1470 7017.5,1250 ; 7050,600 7170,600 7170,765 7050,765 7050,600 ; 7050,780 7170,780 7170,940 7050,940 7050,780 ; 7202.5,1250 7367.5,1250 7367.5,1470 7202.5,1470 7202.5,1250 ; 7297.5,4719 7462.5,4719 7462.5,4939 7297.5,4939 7297.5,4719 ; 7435,3480 7775,3480 7775,3800 7435,3800 7435,3480
Board Outline:
  lines w0: 0,100 ccw(c100,100) 100,0 7900,0 ccw(c7900,100) 8000,100 8000,7900 ccw(c7900,7900) 7900,8000 100,8000 ccw(c100,7900) 0,7900 0,100
  lines w1: 1605,1850 ccw(c1617.5,1862.5) 1630,1850 1630,2150 ccw(c1617.5,2137.5) 1605,2150 1605,1850 ; 1605,2300 ccw(c1617.5,2312.5) 1630,2300 1630,2600 ccw(c1617.5,2587.5) 1605,2600 1605,2300 ; 1605,2750 ccw(c1617.5,2762.5) 1630,2750 1630,3050 ccw(c1617.5,3037.5) 1605,3050 1605,2750 ; 1605,3200 ccw(c1617.5,3212.5) 1630,3200 1630,3500 ccw(c1617.5,3487.5) 1605,3500 1605,3200 ; 1605,3650 ccw(c1617.5,3662.5) 1630,3650 1630,3950 ccw(c1617.5,3937.5) 1605,3950 1605,3650 ; 1680,2075 ccw(c1692.5,2087.5) 1705,2075 1705,2375 ccw(c1692.5,2362.5) 1680,2375 1680,2075 ; 1680,2525 ccw(c1692.5,2537.5) 1705,2525 1705,2825 ccw(c1692.5,2812.5) 1680,2825 1680,2525 ; 1680,2975 ccw(c1692.5,2987.5) 1705,2975 1705,3275 ccw(c1692.5,3262.5) 1680,3275 1680,2975 ; 1680,3425 ccw(c1692.5,3437.5) 1705,3425 1705,3725 ccw(c1692.5,3712.5) 1680,3725 1680,3425 ; 5295,1625 ccw(c5307.5,1637.5) 5320,1625 5320,1925 ccw(c5307.5,1912.5) 5295,1925 5295,1625 ; 5295,2075 ccw(c5307.5,2087.5) 5320,2075 5320,2375 ccw(c5307.5,2362.5) 5295,2375 5295,2075 ; 5295,2525 ccw(c5307.5,2537.5) 5320,2525 5320,2825 ccw(c5307.5,2812.5) 5295,2825 5295,2525 ; 5295,2975 ccw(c5307.5,2987.5) 5320,2975 5320,3275 ccw(c5307.5,3262.5) 5295,3275 5295,2975 ; 5295,3425 ccw(c5307.5,3437.5) 5320,3425 5320,3725 ccw(c5307.5,3712.5) 5295,3725 5295,3425 ; 5370,1850 ccw(c5382.5,1862.5) 5395,1850 5395,2150 ccw(c5382.5,2137.5) 5370,2150 5370,1850 ; 5370,2300 ccw(c5382.5,2312.5) 5395,2300 5395,2600 ccw(c5382.5,2587.5) 5370,2600 5370,2300 ; 5370,2750 ccw(c5382.5,2762.5) 5395,2750 5395,3050 ccw(c5382.5,3037.5) 5370,3050 5370,2750 ; 5370,3200 ccw(c5382.5,3212.5) 5395,3200 5395,3500 ccw(c5382.5,3487.5) 5370,3500 5370,3200 ; 5370,3650 ccw(c5382.5,3662.5) 5395,3650 5395,3950 ccw(c5382.5,3937.5) 5370,3950 5370,3650
  lines w10: 55,-8425 ccw(c55,-8325) 155,-8325 ; 0,100 ccw(c100,100) 100,0 7900,0 ccw(c7900,100) 8000,100 8000,7900 ccw(c7900,7900) 7900,8000 100,8000 ccw(c100,7900) 0,7900 0,100
Drill Drawing:
  drawing of 189 lines, arcs and shapes, not listed
  text "*" at 140,12135 h60
  text "THESE HOLES (1.10MM +/- 0.05MM) ARE FOR PRESS-FIT PART. USE 46.5MIL +/- 1MIL DRILLED HOLES. COPPER THICKNESS IN HOLE 25-50UM." at 235,12080 h100
  text "w" at 9.31,12054.72 h200
  text "^" at 145,11950.01 h60
  text "THESE HOLES (1.48MM +/- 0.05MM) ARE FOR PRESS-FIT PART. USE 63.0MIL +/- 1MIL DRILLED HOLES. COPPER THICKNESS IN HOLE 25-60UM." at 240,11885 h100
  text "w" at 15.85,11866.66 h200
  text "Symbol" at 97.5,11728.94 h72
  text "Count" at 603.38,11728.94 h72
  text "Hole Size" at 1203.22,11728.94 h72
  text "Plated" at 2302.9,11728.94 h72
  text "Hole Type" at 2808.77,11728.94 h72
  text "Drill Layer Pair" at 3542.57,11728.94 h72
  text "Via/Pad" at 5042.13,11728.94 h72
  text "Pad Shape" at 5631.97,11728.94 h72
  text "Hole Tolerance (+)" at 6377.77,11728.94 h72
  text "Hole Tolerance (-)" at 7711.38,11728.94 h72
  text "Hole Length" at 9044.99,11728.94 h72
  text "Routed Path Length" at 10074.69,11728.94 h72
  text "20" at 603.38,11578.94 h60
  text "0.20mm (7.87mil)" at 1203.22,11578.94 h60
  text "PTH" at 2302.9,11578.94 h60
  text "Round" at 2808.77,11578.94 h60
  text "Top Layer - Bottom Layer" at 3542.57,11578.94 h60
  text "Via" at 5042.13,11578.94 h60
  text "Rounded" at 5631.97,11578.94 h60
  text "0.08mm (3.00mil)" at 6377.77,11578.94 h60
  text "0.08mm (3.00mil)" at 7711.38,11578.94 h60
  text "-" at 9044.99,11578.94 h60
  text "-" at 10074.69,11578.94 h60
  text "543" at 603.38,11428.94 h60
  text "0.33mm (13.00mil)" at 1203.22,11428.94 h60
  text "PTH" at 2302.9,11428.94 h60
  text "Round" at 2808.77,11428.94 h60
  text "Top Layer - Bottom Layer" at 3542.57,11428.94 h60
  text "Via" at 5042.13,11428.94 h60
  text "Rounded" at 5631.97,11428.94 h60
  text "0.08mm (3.00mil)" at 6377.77,11428.94 h60
  text "0.08mm (3.00mil)" at 7711.38,11428.94 h60
  text "-" at 9044.99,11428.94 h60
  text "-" at 10074.69,11428.94 h60
  text "A" at 68.41,11418.95 h66.67
  text "76" at 603.38,11278.94 h60
  text "0.71mm (28.00mil)" at 1203.22,11278.94 h60
  text "PTH" at 2302.9,11278.94 h60
  text "Round" at 2808.77,11278.94 h60
  text "Top Layer - Bottom Layer" at 3542.57,11278.94 h60
  text "Via" at 5042.13,11278.94 h60
  text "Rounded" at 5631.97,11278.94 h60
  text "0.08mm (3.00mil)" at 6377.77,11278.94 h60
  text "0.08mm (3.00mil)" at 7711.38,11278.94 h60
  text "-" at 9044.99,11278.94 h60
  text "-" at 10074.69,11278.94 h60
  text "32" at 603.38,11128.94 h60
  text "0.84mm (33.07mil)" at 1203.22,11128.94 h60
  text "PTH" at 2302.9,11128.94 h60
  text "Round" at 2808.77,11128.94 h60
  text "Top Layer - Bottom Layer" at 3542.57,11128.94 h60
  text "Pad" at 5042.13,11128.94 h60
  text "(Mixed)" at 5631.97,11128.94 h60
  text "0.08mm (3.00mil)" at 6377.77,11128.94 h60
  text "0.08mm (3.00mil)" at 7711.38,11128.94 h60
  text "-" at 9044.99,11128.94 h60
  text "-" at 10074.69,11128.94 h60
  text "18" at 603.38,10978.94 h60
  text "1.00mm (39.37mil)" at 1203.22,10978.94 h60
  text "PTH" at 2302.9,10978.94 h60
  text "Round" at 2808.77,10978.94 h60
  text "Top Layer - Bottom Layer" at 3542.57,10978.94 h60
  text "Pad" at 5042.13,10978.94 h60
  text "(Mixed)" at 5631.97,10978.94 h60
  text "0.08mm (3.00mil)" at 6377.77,10978.94 h60
  text "0.08mm (3.00mil)" at 7711.38,10978.94 h60
  text "-" at 9044.99,10978.94 h60
  text "-" at 10074.69,10978.94 h60
  text "3" at 603.38,10828.94 h60
  text "1.00mm (39.37mil)" at 1203.22,10828.94 h60
  text "PTH" at 2302.9,10828.94 h60
  text "Slot" at 2808.77,10828.94 h60
  text "Top Layer - Bottom Layer" at 3542.57,10828.94 h60
  text "Pad" at 5042.13,10828.94 h60
  text "Rectangle" at 5631.97,10828.94 h60
  text "0.08mm (3.00mil)" at 6377.77,10828.94 h60
  text "0.08mm (3.00mil)" at 7711.38,10828.94 h60
  text "1.60mm (62.99mil)" at 9044.99,10828.94 h60
  text "0.60mm (23.62mil)" at 10074.69,10828.94 h60
  text "B" at 68.41,10818.95 h66.67
  text "23" at 603.38,10678.94 h60
  text "1.10mm (43.31mil)" at 1203.22,10678.94 h60
  text "PTH" at 2302.9,10678.94 h60
  text "Round" at 2808.77,10678.94 h60
  text "Top Layer - Bottom Layer" at 3542.57,10678.94 h60
  text "Pad" at 5042.13,10678.94 h60
  text "Rounded" at 5631.97,10678.94 h60
  text "0.05mm (1.97mil)" at 6377.77,10678.94 h60
  text "0.05mm (1.97mil)" at 7711.38,10678.94 h60
  text "-" at 9044.99,10678.94 h60
  text "-" at 10074.69,10678.94 h60
  text "*" at -90,10575 h60
  text "18" at 603.38,10528.94 h60
  text "1.10mm (43.31mil)" at 1203.22,10528.94 h60
  text "PTH" at 2302.9,10528.94 h60
  text "Round" at 2808.77,10528.94 h60
  text "Top Layer - Bottom Layer" at 3542.57,10528.94 h60
  text "Pad" at 5042.13,10528.94 h60
  text "(Mixed)" at 5631.97,10528.94 h60
  text "0.08mm (3.00mil)" at 6377.77,10528.94 h60
  text "0.08mm (3.00mil)" at 7711.38,10528.94 h60
  text "-" at 9044.99,10528.94 h60
  text "-" at 10074.69,10528.94 h60
  text "D" at 68.41,10518.95 h66.67
  text "w" at -220.69,10494.72 h200
  text "30" at 603.38,10378.94 h60
  text "1.15mm (45.28mil)" at 1203.22,10378.94 h60
  text "PTH" at 2302.9,10378.94 h60
  text "Round" at 2808.77,10378.94 h60
  text "Top Layer - Bottom Layer" at 3542.57,10378.94 h60
  text "Pad" at 5042.13,10378.94 h60
  text "Rounded" at 5631.97,10378.94 h60
  text "0.08mm (3.00mil)" at 6377.77,10378.94 h60
  text "0.08mm (3.00mil)" at 7711.38,10378.94 h60
  text "-" at 9044.99,10378.94 h60
  text "-" at 10074.69,10378.94 h60
  text "4" at 603.38,10228.94 h60
  text "1.19mm (47.00mil)" at 1203.22,10228.94 h60
  text "PTH" at 2302.9,10228.94 h60
  text "Round" at 2808.77,10228.94 h60
  text "Top Layer - Bottom Layer" at 3542.57,10228.94 h60
  text "Pad" at 5042.13,10228.94 h60
  text "Rounded" at 5631.97,10228.94 h60
  text "0.08mm (3.00mil)" at 6377.77,10228.94 h60
  text "0.08mm (3.00mil)" at 7711.38,10228.94 h60
  text "-" at 9044.99,10228.94 h60
  text "-" at 10074.69,10228.94 h60
  text "C" at 68.41,10218.95 h66.67
  text "9" at 603.38,10078.94 h60
  text "1.20mm (47.24mil)" at 1203.22,10078.94 h60
  text "PTH" at 2302.9,10078.94 h60
  text "Round" at 2808.77,10078.94 h60
  text "Top Layer - Bottom Layer" at 3542.57,10078.94 h60
  text "Pad" at 5042.13,10078.94 h60
  text "Rounded" at 5631.97,10078.94 h60
  text "0.08mm (3.00mil)" at 6377.77,10078.94 h60
  text "0.08mm (3.00mil)" at 7711.38,10078.94 h60
  text "-" at 9044.99,10078.94 h60
  text "-" at 10074.69,10078.94 h60
  text "2" at 603.38,9928.94 h60
  text "1.27mm (50.00mil)" at 1203.22,9928.94 h60
  text "NPTH" at 2302.9,9928.94 h60
  text "Round" at 2808.77,9928.94 h60
  text "Top Layer - Bottom Layer" at 3542.57,9928.94 h60
  text "Pad" at 5042.13,9928.94 h60
  text "Rounded" at 5631.97,9928.94 h60
  text "0.08mm (3.00mil)" at 6377.77,9928.94 h60
  text "0.08mm (3.00mil)" at 7711.38,9928.94 h60
  text "-" at 9044.99,9928.94 h60
  text "-" at 10074.69,9928.94 h60
  text "4" at 603.38,9778.94 h60
  text "1.27mm (50.00mil)" at 1203.22,9778.94 h60
  text "PTH" at 2302.9,9778.94 h60
  text "Round" at 2808.77,9778.94 h60
  text "Top Layer - Bottom Layer" at 3542.57,9778.94 h60
  text "Pad" at 5042.13,9778.94 h60
  text "(Mixed)" at 5631.97,9778.94 h60
  text "0.08mm (3.00mil)" at 6377.77,9778.94 h60
  text "0.08mm (3.00mil)" at 7711.38,9778.94 h60
  text "-" at 9044.99,9778.94 h60
  text "-" at 10074.69,9778.94 h60
  text "10" at 603.38,9628.94 h60
  text "1.40mm (55.12mil)" at 1203.22,9628.94 h60
  text "PTH" at 2302.9,9628.94 h60
  text "Round" at 2808.77,9628.94 h60
  text "Top Layer - Bottom Layer" at 3542.57,9628.94 h60
  text "Pad" at 5042.13,9628.94 h60
  text "(Mixed)" at 5631.97,9628.94 h60
  text "0.08mm (3.00mil)" at 6377.77,9628.94 h60
  text "0.08mm (3.00mil)" at 7711.38,9628.94 h60
  text "-" at 9044.99,9628.94 h60
  text "-" at 10074.69,9628.94 h60
  text "^" at -100,9525.01 h60
  text "40" at 603.38,9478.94 h60
  text "1.48mm (58.07mil)" at 1203.22,9478.94 h60
  text "PTH" at 2302.9,9478.94 h60
  text "Round" at 2808.77,9478.94 h60
  text "Top Layer - Bottom Layer" at 3542.57,9478.94 h60
  text "Pad" at 5042.13,9478.94 h60
  text "Rounded" at 5631.97,9478.94 h60
  text "0.05mm (1.97mil)" at 6377.77,9478.94 h60
  text "0.05mm (1.97mil)" at 7711.38,9478.94 h60
  text "-" at 9044.99,9478.94 h60
  text "-" at 10074.69,9478.94 h60
  text "E" at 68.41,9468.95 h66.67
  text "w" at -229.15,9441.66 h200
  text "15" at 603.38,9328.94 h60
  text "1.60mm (62.99mil)" at 1203.22,9328.94 h60
  text "PTH" at 2302.9,9328.94 h60
  text "Round" at 2808.77,9328.94 h60
  text "Top Layer - Bottom Layer" at 3542.57,9328.94 h60
  text "Pad" at 5042.13,9328.94 h60
  text "Rounded" at 5631.97,9328.94 h60
  text "0.08mm (3.00mil)" at 6377.77,9328.94 h60
  text "0.08mm (3.00mil)" at 7711.38,9328.94 h60
  text "-" at 9044.99,9328.94 h60
  text "-" at 10074.69,9328.94 h60
  text "30" at 603.38,9178.94 h60
  text "2.00mm (78.74mil)" at 1203.22,9178.94 h60
  text "PTH" at 2302.9,9178.94 h60
  text "Round" at 2808.77,9178.94 h60
  text "Top Layer - Bottom Layer" at 3542.57,9178.94 h60
  text "Pad" at 5042.13,9178.94 h60
  text "Rounded" at 5631.97,9178.94 h60
  text "0.08mm (3.00mil)" at 6377.77,9178.94 h60
  text "0.08mm (3.00mil)" at 7711.38,9178.94 h60
  text "-" at 9044.99,9178.94 h60
  text "-" at 10074.69,9178.94 h60
  text "2" at 603.38,9028.94 h60
  text "3.05mm (120.08mil)" at 1203.22,9028.94 h60
  text "PTH" at 2302.9,9028.94 h60
  text "Round" at 2808.77,9028.94 h60
  text "Top Layer - Bottom Layer" at 3542.57,9028.94 h60
  text "Pad" at 5042.13,9028.94 h60
  text "Rounded" at 5631.97,9028.94 h60
  text "0.13mm (5.00mil)" at 6377.77,9028.94 h60
  text "0.13mm (5.00mil)" at 7711.38,9028.94 h60
  text "-" at 9044.99,9028.94 h60
  text "-" at 10074.69,9028.94 h60
  text "8" at 603.38,8878.94 h60
  text "4.50mm (177.17mil)" at 1203.22,8878.94 h60
  text "PTH" at 2302.9,8878.94 h60
  text "Round" at 2808.77,8878.94 h60
  text "Top Layer - Bottom Layer" at 3542.57,8878.94 h60
  text "Pad" at 5042.13,8878.94 h60
  text "Rounded" at 5631.97,8878.94 h60
  text "0.13mm (5.00mil)" at 6377.77,8878.94 h60
  text "0.13mm (5.00mil)" at 7711.38,8878.94 h60
  text "-" at 9044.99,8878.94 h60
  text "-" at 10074.69,8878.94 h60
  text "2" at 603.38,8728.94 h60
  text "9.00mm (354.33mil)" at 1203.22,8728.94 h60
  text "NPTH" at 2302.9,8728.94 h60
  text "Round" at 2808.77,8728.94 h60
  text "Top Layer - Bottom Layer" at 3542.57,8728.94 h60
  text "Pad" at 5042.13,8728.94 h60
  text "Rounded" at 5631.97,8728.94 h60
  text "0.13mm (5.00mil)" at 6377.77,8728.94 h60
  text "0.13mm (5.00mil)" at 7711.38,8728.94 h60
  text "-" at 9044.99,8728.94 h60
  text "-" at 10074.69,8728.94 h60
  text "F" at 68.41,8718.95 h66.67
  text "889 Total" at 603.38,8578.94 h60
  text "Slot definitions :" at 97.5,8433.97 h60
  text "Routed Path Length" at 1130.19,8433.97 h60
  text "= Calculated from tool start centre position to tool end centre position." at 2232.86,8433.97 h60
  text "Hole Length" at 1130.19,8333.99 h60
  text "= Routed Path Length + Tool Size = Slot length as defined in the PCB layout" at 1822.99,8333.99 h60

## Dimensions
100,8000 to 100,0 on Drill Drawing
0,100 to 8000,100 on Drill Drawing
